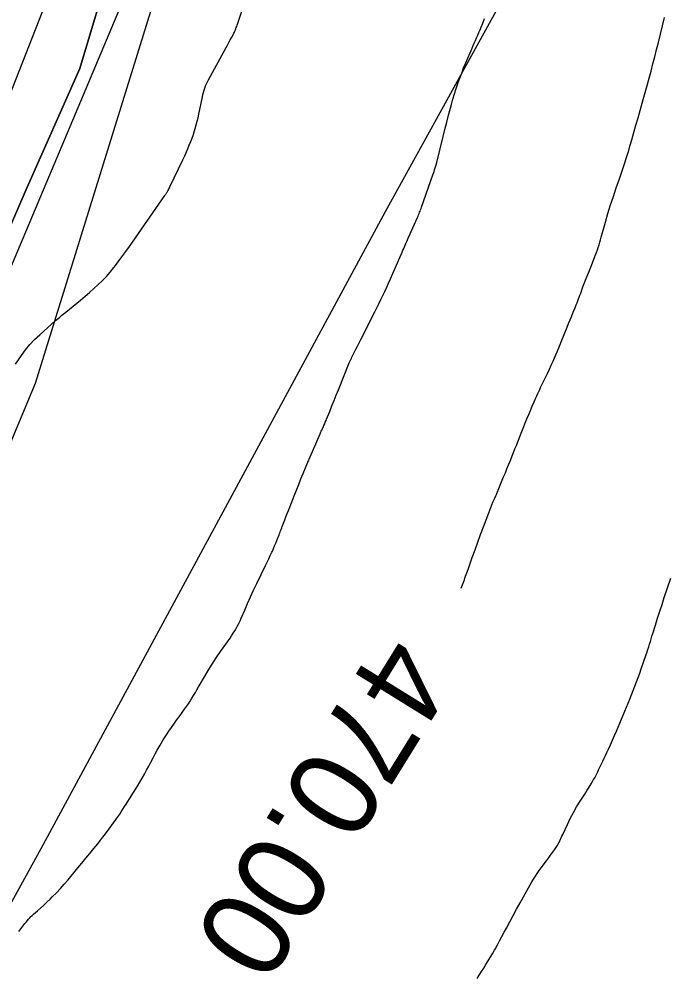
# Model space of a CAD drawing. Extents: x -629976 to -626966, y -1086511 to -1082952.
# Drawn here: x -629162 to -629088.7, y -1085684.5 to -1085576.7 of the extents above; entities that cross this region are included whole.
import ezdxf

# ---------------------------------------------------------------- set-up
doc = ezdxf.new("R2010")
doc.units = 0
for name, color, linetype in [('01_DOPRAVA', 7, 'Continuous'), ('01_VRSTEVNICE', 7, 'Continuous'), ('02_KULTURY STAV', 7, 'Continuous'), ('04_ZPF_OP_ORGAN', 7, 'Continuous'), ('05_VHO_MELIORACE', 7, 'Continuous'), ('06_KRAJ_ZELEŇ_STAV', 7, 'Continuous'), ('07_ELEKTRO', 7, 'Continuous')]:
    doc.layers.add(name, color=color, linetype=linetype)

msp = doc.modelspace()

# ---------------------------------------------------------------- linework, layer by layer
at = {"layer": '01_DOPRAVA'}
msp.add_lwpolyline([(-629186.14, -1085155.29), (-629171, -1085319.71), (-629165.07, -1085394.42), (-629156.22, -1085497.41), (-629154.21, -1085534.54), (-629154.55, -1085552.73), (-629159.04, -1085574.9), (-629167.26, -1085595.73), (-629273.28, -1085839.63), (-629291.35, -1085878.33), (-629321.61, -1085934.35), (-629344.45, -1085974.65), (-629362.33, -1085999.9), (-629377.88, -1086019.46), (-629390.59, -1086039.03), (-629413.49, -1086083.51)], dxfattribs=at)
at = {"layer": '01_VRSTEVNICE'}
for points in [[(-629162.41, -1085615.46), (-629161.75, -1085614.49), (-629161.29, -1085613.87), (-629160.79, -1085613.26), (-629160.26, -1085612.7), (-629159.69, -1085612.16), (-629157.91, -1085610.57), (-629157.76, -1085610.45), (-629157.62, -1085610.32), (-629157.47, -1085610.2), (-629157.33, -1085610.09), (-629157.18, -1085609.97), (-629157.03, -1085609.85), (-629156.88, -1085609.73), (-629156.74, -1085609.61), (-629155.09, -1085608.26), (-629154.59, -1085607.83), (-629154.09, -1085607.4), (-629153.59, -1085606.97), (-629153.11, -1085606.52), (-629152.64, -1085606.07), (-629152.18, -1085605.59), (-629151.75, -1085605.1), (-629151.34, -1085604.59), (-629151.28, -1085604.51), (-629150.85, -1085603.95), (-629150.43, -1085603.38), (-629150.01, -1085602.81), (-629149.6, -1085602.23), (-629145.6, -1085596.49), (-629145.56, -1085596.44), (-629145.53, -1085596.39), (-629145.49, -1085596.33), (-629145.45, -1085596.28), (-629145.42, -1085596.22), (-629145.38, -1085596.17), (-629145.35, -1085596.11), (-629145.32, -1085596.06), (-629145.26, -1085595.95), (-629145.2, -1085595.85), (-629145.15, -1085595.74), (-629145.09, -1085595.63), (-629145.04, -1085595.52), (-629143.58, -1085592.48), (-629143.37, -1085592.03), (-629143.17, -1085591.58), (-629142.98, -1085591.12), (-629142.79, -1085590.66), (-629142.73, -1085590.52), (-629142.58, -1085590.13), (-629142.44, -1085589.74), (-629142.31, -1085589.34), (-629142.19, -1085588.94), (-629142.08, -1085588.54), (-629141.98, -1085588.14), (-629141.88, -1085587.74), (-629141.79, -1085587.33), (-629141.39, -1085585.4), (-629141.33, -1085585.15), (-629141.27, -1085584.9), (-629141.19, -1085584.65), (-629141.11, -1085584.41), (-629141.02, -1085584.17), (-629140.92, -1085583.94), (-629140.81, -1085583.71), (-629140.69, -1085583.48), (-629138.72, -1085579.86), (-629138.56, -1085579.57), (-629138.4, -1085579.28), (-629138.25, -1085578.99), (-629138.09, -1085578.7), (-629137.9, -1085578.35), (-629137.84, -1085578.23), (-629137.78, -1085578.11), (-629137.72, -1085577.99), (-629137.67, -1085577.86), (-629137.62, -1085577.74), (-629137.57, -1085577.61), (-629137.52, -1085577.48), (-629137.47, -1085577.35), (-629136.56, -1085574.65)], [(-629162.04, -1085679.28), (-629161.47, -1085678.54), (-629161.34, -1085678.38), (-629161.21, -1085678.22), (-629161.08, -1085678.07), (-629160.95, -1085677.91), (-629160.81, -1085677.76), (-629160.67, -1085677.61), (-629160.52, -1085677.47), (-629160.37, -1085677.33), (-629159.95, -1085676.96), (-629159.58, -1085676.64), (-629159.23, -1085676.31), (-629158.87, -1085675.98), (-629158.52, -1085675.64), (-629158.27, -1085675.4), (-629157.81, -1085674.93), (-629157.35, -1085674.45), (-629156.92, -1085673.96), (-629156.49, -1085673.46), (-629155.39, -1085672.12), (-629154.94, -1085671.58), (-629154.49, -1085671.04), (-629154.05, -1085670.5), (-629153.6, -1085669.96), (-629153.15, -1085669.42), (-629152.72, -1085668.87), (-629152.29, -1085668.31), (-629151.87, -1085667.74), (-629151.08, -1085666.65), (-629150.88, -1085666.37), (-629150.69, -1085666.09), (-629150.51, -1085665.81), (-629150.32, -1085665.53), (-629150.14, -1085665.24), (-629149.96, -1085664.95), (-629149.78, -1085664.66), (-629149.6, -1085664.37), (-629148.7, -1085662.94), (-629148.43, -1085662.5), (-629148.16, -1085662.05), (-629147.91, -1085661.6), (-629147.66, -1085661.14), (-629147.42, -1085660.68), (-629147.17, -1085660.22), (-629146.93, -1085659.76), (-629146.69, -1085659.3), (-629146.47, -1085658.9), (-629146.15, -1085658.32), (-629145.8, -1085657.74), (-629145.44, -1085657.17), (-629145.07, -1085656.62), (-629145.06, -1085656.6), (-629144.67, -1085656.06), (-629144.29, -1085655.52), (-629143.9, -1085654.98), (-629143.51, -1085654.44), (-629143.17, -1085653.96), (-629142.96, -1085653.66), (-629142.75, -1085653.36), (-629142.56, -1085653.04), (-629142.37, -1085652.73), (-629142.18, -1085652.41), (-629142, -1085652.09), (-629141.81, -1085651.77), (-629141.63, -1085651.45), (-629141.16, -1085650.63), (-629140.73, -1085649.91), (-629140.29, -1085649.2), (-629139.82, -1085648.49), (-629139.35, -1085647.8), (-629138.28, -1085646.28), (-629138.1, -1085646.01), (-629137.92, -1085645.74), (-629137.75, -1085645.47), (-629137.59, -1085645.19), (-629137.43, -1085644.91), (-629137.28, -1085644.63), (-629137.14, -1085644.33), (-629137.01, -1085644.04), (-629136.62, -1085643.12), (-629136.3, -1085642.37), (-629135.96, -1085641.62), (-629135.62, -1085640.87), (-629135.26, -1085640.13), (-629134.27, -1085638.1), (-629134.09, -1085637.73), (-629133.92, -1085637.37), (-629133.75, -1085637), (-629133.59, -1085636.63), (-629133.52, -1085636.49), (-629133.39, -1085636.19), (-629133.26, -1085635.89), (-629133.14, -1085635.59), (-629133.01, -1085635.29), (-629132.89, -1085635), (-629132.83, -1085634.84), (-629132.77, -1085634.68), (-629132.71, -1085634.53), (-629132.65, -1085634.37), (-629132.59, -1085634.21), (-629132.53, -1085634.05), (-629132.47, -1085633.89), (-629132.41, -1085633.74), (-629132.27, -1085633.34), (-629132.13, -1085632.99), (-629132, -1085632.63), (-629131.86, -1085632.28), (-629131.72, -1085631.93), (-629131.3, -1085630.89), (-629131.05, -1085630.27), (-629130.8, -1085629.64), (-629130.55, -1085629.01), (-629130.3, -1085628.38), (-629130.05, -1085627.75), (-629129.79, -1085627.13), (-629129.53, -1085626.5), (-629129.27, -1085625.88), (-629128.14, -1085623.29), (-629128.09, -1085623.19), (-629128.05, -1085623.09), (-629128.01, -1085622.99), (-629127.96, -1085622.9), (-629127.92, -1085622.8), (-629127.87, -1085622.71), (-629127.83, -1085622.61), (-629127.78, -1085622.51), (-629127.71, -1085622.35), (-629127.63, -1085622.18), (-629127.56, -1085622), (-629127.48, -1085621.82), (-629127.41, -1085621.64), (-629127.06, -1085620.78), (-629126.82, -1085620.17), (-629126.57, -1085619.56), (-629126.33, -1085618.95), (-629126.08, -1085618.34), (-629124.86, -1085615.31), (-629124.83, -1085615.23), (-629124.8, -1085615.16), (-629124.77, -1085615.09), (-629124.73, -1085615.02), (-629124.7, -1085614.95), (-629124.67, -1085614.88), (-629124.63, -1085614.81), (-629124.6, -1085614.74), (-629124.3, -1085614.15), (-629124.11, -1085613.79), (-629123.93, -1085613.43), (-629123.74, -1085613.07), (-629123.56, -1085612.7), (-629121.98, -1085609.58), (-629121.75, -1085609.12), (-629121.53, -1085608.66), (-629121.3, -1085608.2), (-629121.08, -1085607.74), (-629120.86, -1085607.28), (-629120.65, -1085606.81), (-629120.44, -1085606.34), (-629120.23, -1085605.88), (-629118.91, -1085602.85), (-629118.83, -1085602.65), (-629118.74, -1085602.46), (-629118.66, -1085602.26), (-629118.58, -1085602.07), (-629118.49, -1085601.88), (-629118.41, -1085601.68), (-629118.32, -1085601.49), (-629118.24, -1085601.29), (-629117.2, -1085598.96), (-629117.13, -1085598.82), (-629117.07, -1085598.68), (-629117.01, -1085598.53), (-629116.95, -1085598.38), (-629116.89, -1085598.24), (-629116.84, -1085598.09), (-629116.78, -1085597.94), (-629116.73, -1085597.79), (-629115.47, -1085594.18), (-629115.4, -1085593.99), (-629115.33, -1085593.79), (-629115.27, -1085593.59), (-629115.2, -1085593.39), (-629115.1, -1085593.06), (-629115.09, -1085593.03), (-629115.08, -1085592.99), (-629115.07, -1085592.96), (-629115.06, -1085592.92), (-629115.05, -1085592.89), (-629115.04, -1085592.85), (-629115.03, -1085592.82), (-629115.02, -1085592.78), (-629114.31, -1085589.87), (-629114.11, -1085589.06), (-629113.91, -1085588.26), (-629113.7, -1085587.46), (-629113.49, -1085586.65), (-629113.38, -1085586.24), (-629113.21, -1085585.65), (-629113.03, -1085585.06), (-629112.85, -1085584.47), (-629112.65, -1085583.89), (-629112.44, -1085583.3), (-629112.22, -1085582.73), (-629112, -1085582.15), (-629111.76, -1085581.58), (-629111.06, -1085579.93), (-629110.93, -1085579.63), (-629110.8, -1085579.34), (-629110.67, -1085579.04), (-629110.54, -1085578.74), (-629110.4, -1085578.45), (-629110.28, -1085578.15), (-629110.15, -1085577.85), (-629110.03, -1085577.55), (-629109.86, -1085577.1), (-629109.66, -1085576.57)], [(-629112.28, -1085640.66), (-629112.07, -1085640.1), (-629111.99, -1085639.91), (-629111.92, -1085639.72), (-629111.85, -1085639.53), (-629111.78, -1085639.33), (-629111.71, -1085639.14), (-629111.64, -1085638.95), (-629111.57, -1085638.75), (-629111.5, -1085638.56), (-629111.03, -1085637.21), (-629110.72, -1085636.34), (-629110.41, -1085635.48), (-629110.09, -1085634.61), (-629109.77, -1085633.75), (-629109.18, -1085632.18), (-629109.07, -1085631.88), (-629108.95, -1085631.58), (-629108.82, -1085631.28), (-629108.7, -1085630.98), (-629108.54, -1085630.63), (-629108.49, -1085630.51), (-629108.43, -1085630.39), (-629108.38, -1085630.26), (-629108.32, -1085630.14), (-629108.27, -1085630.02), (-629108.22, -1085629.9), (-629108.17, -1085629.77), (-629108.11, -1085629.65), (-629107.5, -1085628.14), (-629107.31, -1085627.68), (-629107.13, -1085627.23), (-629106.94, -1085626.77), (-629106.75, -1085626.31), (-629106.7, -1085626.17), (-629106.54, -1085625.78), (-629106.38, -1085625.39), (-629106.23, -1085624.99), (-629106.07, -1085624.6), (-629105.92, -1085624.21), (-629105.77, -1085623.82), (-629105.61, -1085623.42), (-629105.45, -1085623.03), (-629104.88, -1085621.61), (-629104.68, -1085621.13), (-629104.48, -1085620.66), (-629104.28, -1085620.19), (-629104.08, -1085619.72), (-629103.87, -1085619.24), (-629103.77, -1085619.01), (-629103.67, -1085618.78), (-629103.56, -1085618.55), (-629103.45, -1085618.32), (-629103.35, -1085618.09), (-629103.24, -1085617.86), (-629103.13, -1085617.64), (-629103.01, -1085617.41), (-629102.79, -1085616.96), (-629102.57, -1085616.5), (-629102.35, -1085616.04), (-629102.14, -1085615.58), (-629101.94, -1085615.12), (-629101.78, -1085614.74), (-629101.5, -1085614.08), (-629101.22, -1085613.43), (-629100.95, -1085612.77), (-629100.69, -1085612.11), (-629100.36, -1085611.3), (-629100.19, -1085610.88), (-629100.02, -1085610.46), (-629099.85, -1085610.04), (-629099.68, -1085609.62), (-629099.51, -1085609.22), (-629099.42, -1085609), (-629099.33, -1085608.78), (-629099.25, -1085608.57), (-629099.16, -1085608.35), (-629099.08, -1085608.13), (-629099, -1085607.91), (-629098.92, -1085607.69), (-629098.83, -1085607.47), (-629098.58, -1085606.78), (-629098.37, -1085606.22), (-629098.15, -1085605.66), (-629097.93, -1085605.1), (-629097.71, -1085604.54), (-629097.28, -1085603.46), (-629097.17, -1085603.18), (-629097.06, -1085602.9), (-629096.96, -1085602.62), (-629096.86, -1085602.33), (-629096.77, -1085602.04), (-629096.69, -1085601.75), (-629096.6, -1085601.47), (-629096.52, -1085601.18), (-629096.05, -1085599.51), (-629095.77, -1085598.53), (-629095.47, -1085597.56), (-629095.15, -1085596.59), (-629094.83, -1085595.63), (-629094.47, -1085594.62), (-629094.31, -1085594.16), (-629094.16, -1085593.71), (-629094.01, -1085593.25), (-629093.86, -1085592.8), (-629093.71, -1085592.34), (-629093.57, -1085591.88), (-629093.44, -1085591.42), (-629093.3, -1085590.96), (-629093.1, -1085590.23), (-629092.86, -1085589.4), (-629092.63, -1085588.57), (-629092.39, -1085587.74), (-629092.15, -1085586.92), (-629091.8, -1085585.71), (-629091.57, -1085584.91), (-629091.35, -1085584.11), (-629091.13, -1085583.31), (-629090.92, -1085582.5), (-629090.71, -1085581.7), (-629090.5, -1085580.89), (-629090.3, -1085580.08), (-629090.1, -1085579.28), (-629089.41, -1085576.47)], [(-629110.49, -1085684.57), (-629110.24, -1085684.18), (-629109.99, -1085683.79), (-629109.74, -1085683.39), (-629109.49, -1085683), (-629109.25, -1085682.6), (-629109.01, -1085682.2), (-629108.77, -1085681.8), (-629108.54, -1085681.39), (-629108.47, -1085681.26), (-629108.21, -1085680.79), (-629107.95, -1085680.32), (-629107.69, -1085679.84), (-629107.44, -1085679.36), (-629107.19, -1085678.9), (-629106.81, -1085678.19), (-629106.43, -1085677.48), (-629106.04, -1085676.78), (-629105.66, -1085676.07), (-629104.9, -1085674.7), (-629104.71, -1085674.36), (-629104.52, -1085674.03), (-629104.33, -1085673.71), (-629104.13, -1085673.38), (-629103.93, -1085673.06), (-629103.72, -1085672.74), (-629103.5, -1085672.43), (-629103.27, -1085672.12), (-629102.68, -1085671.33), (-629102.45, -1085671.02), (-629102.23, -1085670.71), (-629102, -1085670.39), (-629101.78, -1085670.08), (-629101.56, -1085669.76), (-629101.46, -1085669.6), (-629101.36, -1085669.43), (-629101.27, -1085669.26), (-629101.18, -1085669.08), (-629101.1, -1085668.91), (-629101.02, -1085668.73), (-629100.94, -1085668.55), (-629100.85, -1085668.38), (-629100.33, -1085667.24), (-629100.01, -1085666.57), (-629099.66, -1085665.91), (-629099.29, -1085665.27), (-629098.9, -1085664.63), (-629098.53, -1085664.06), (-629098.31, -1085663.72), (-629098.1, -1085663.37), (-629097.88, -1085663.03), (-629097.67, -1085662.68), (-629097.51, -1085662.41), (-629097.38, -1085662.2), (-629097.26, -1085661.98), (-629097.14, -1085661.76), (-629097.03, -1085661.53), (-629096.92, -1085661.31), (-629096.82, -1085661.08), (-629096.71, -1085660.86), (-629096.6, -1085660.63), (-629096.5, -1085660.44), (-629096.35, -1085660.11), (-629096.19, -1085659.79), (-629096.04, -1085659.47), (-629095.89, -1085659.14), (-629095.72, -1085658.78), (-629095.48, -1085658.27), (-629095.25, -1085657.76), (-629095.03, -1085657.25), (-629094.81, -1085656.74), (-629093.51, -1085653.61), (-629093.31, -1085653.13), (-629093.12, -1085652.65), (-629092.93, -1085652.17), (-629092.73, -1085651.69), (-629092.55, -1085651.21), (-629092.36, -1085650.72), (-629092.19, -1085650.24), (-629092.02, -1085649.75), (-629091.47, -1085648.14), (-629091.37, -1085647.84), (-629091.27, -1085647.55), (-629091.18, -1085647.25), (-629091.09, -1085646.95), (-629091, -1085646.66), (-629090.91, -1085646.36), (-629090.82, -1085646.06), (-629090.73, -1085645.76), (-629090.43, -1085644.81), (-629090.18, -1085644.04), (-629089.94, -1085643.26), (-629089.68, -1085642.49), (-629089.43, -1085641.72), (-629088.69, -1085639.54)]]:
    msp.add_lwpolyline(points, dxfattribs=at)
at = {"layer": '02_KULTURY STAV'}
for points in [[(-629169.78, -1085266.7), (-629163.79, -1085342.02), (-629156.55, -1085427.04), (-629152.18, -1085475.9), (-629147.92, -1085533), (-629147.63, -1085542.4), (-629148.46, -1085554.93), (-629151.53, -1085570.02), (-629155.18, -1085582.22), (-629161.19, -1085595.81), (-629188.91, -1085659.92), (-629211.68, -1085712), (-629232.83, -1085761.45), (-629257.05, -1085815.24), (-629272.65, -1085851.58), (-629282.45, -1085873.36), (-629288.44, -1085885.49), (-629290.08, -1085888.82), (-629315.26, -1085933.92)], [(-629257.05, -1085815.24), (-629232.83, -1085761.45), (-629211.68, -1085712), (-629188.91, -1085659.92), (-629161.19, -1085595.81), (-629155.18, -1085582.22), (-629151.53, -1085570.02), (-629148.46, -1085554.93), (-629147.63, -1085542.4), (-629147.92, -1085533), (-629152.18, -1085475.9), (-629156.55, -1085427.04), (-629163.79, -1085342.02), (-629169.78, -1085266.7)]]:
    msp.add_lwpolyline(points, dxfattribs=at)
at = {"layer": '04_ZPF_OP_ORGAN'}
msp.add_lwpolyline([(-629257.05, -1085815.24), (-629232.83, -1085761.45), (-629211.68, -1085712), (-629188.91, -1085659.92), (-629161.19, -1085595.81), (-629155.18, -1085582.22), (-629151.53, -1085570.02), (-629148.46, -1085554.93), (-629147.63, -1085542.4), (-629147.92, -1085533), (-629152.18, -1085475.9), (-629156.55, -1085427.04), (-629163.79, -1085342.02), (-629169.78, -1085266.7)], dxfattribs=at)
at = {"layer": '05_VHO_MELIORACE'}
msp.add_lwpolyline([(-629162.37, -1085268.86), (-629155.65, -1085324.31), (-629149.44, -1085396.5), (-629141.88, -1085543.64), (-629146.9, -1085574.7), (-629160.2, -1085617.64), (-629192.97, -1085696.19), (-629235.89, -1085791.24), (-629285.31, -1085885.26)], dxfattribs=at)
msp.add_lwpolyline([(-629162.37, -1085268.86), (-629155.65, -1085324.31), (-629149.44, -1085396.5), (-629141.88, -1085543.64), (-629146.9, -1085574.7), (-629160.2, -1085617.64), (-629192.97, -1085696.19), (-629235.89, -1085791.24), (-629285.31, -1085885.26)], dxfattribs=at)
at = {"layer": '06_KRAJ_ZELEŇ_STAV'}
msp.add_lwpolyline([(-628988.71, -1084748.38), (-629051.42, -1084828.28), (-629097.41, -1084875.15), (-629123, -1084914.2), (-629167.27, -1084999.44), (-629178.12, -1085033.72), (-629184.19, -1085072.78), (-629169.66, -1085209.14), (-629153.56, -1085421.03), (-629144.5, -1085529.14), (-629146.24, -1085551.46), (-629150.7, -1085575.51), (-629164.33, -1085607.75), (-629227.48, -1085755.28), (-629273.11, -1085861.69), (-629294.68, -1085907.81), (-629348.96, -1086002.53)], dxfattribs=at)
at = {"layer": '07_ELEKTRO'}
msp.add_lwpolyline([(-629360.18, -1086040.04), (-629312.89, -1085949.85), (-629276.42, -1085883.29), (-629236.58, -1085810.66), (-629197.83, -1085739.58), (-629159.31, -1085669.55), (-629120.79, -1085598.3), (-629080.58, -1085525.41), (-629058.22, -1085467.96), (-629031.57, -1085400.62), (-629001.79, -1085325.87), (-628974.95, -1085257.74), (-628948.77, -1085191.58), (-628921.19, -1085121.43), (-628840.51, -1085026.06), (-628791.45, -1084968.55), (-628741.2, -1084909.32), (-628697.3, -1084857.84), (-628699.64, -1084807.05), (-628700.92, -1084758.55)], dxfattribs=at)

# ---------------------------------------------------------------- texts
at = {"layer": '01_VRSTEVNICE'}
msp.add_text('470.00', height=10, rotation=238.2396, dxfattribs=at).set_placement((-629121.1, -1085645.41))

doc.saveas('drawing.dxf')
